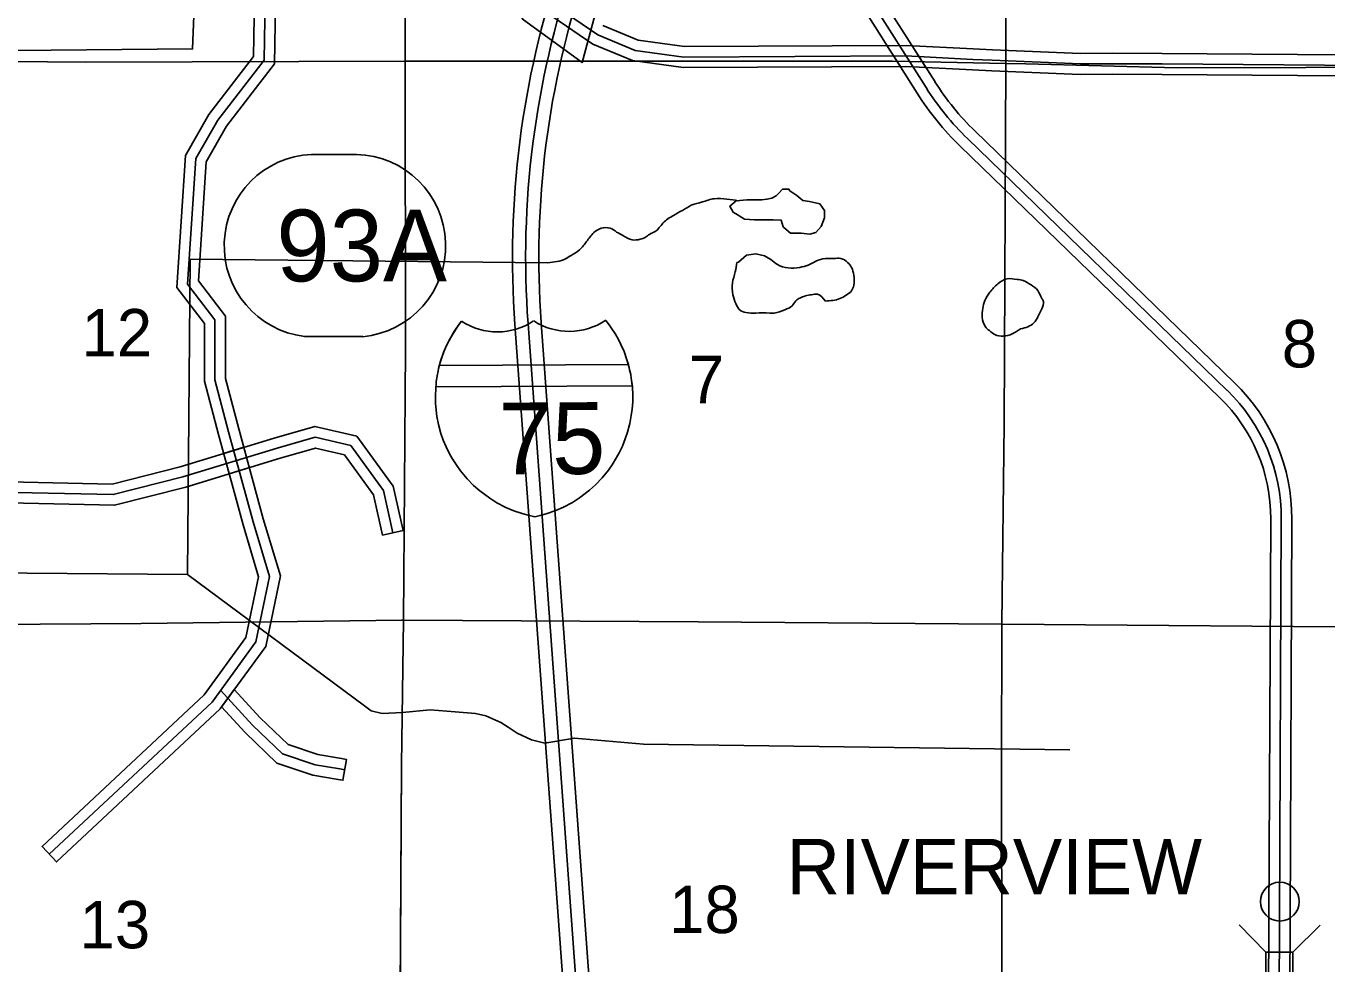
# Model space of a CAD drawing. Extents: x 380424 to 701066, y 1117407 to 1412949.
# Drawn here: x 538699 to 551026, y 1285659 to 1294552 of the extents above; entities that cross this region are included whole.
import ezdxf

# ---------------------------------------------------------------- set-up
doc = ezdxf.new("R2010")
doc.units = 0
for name, color, linetype in [('Bridges and Drawbridges US Highways', 7, 'Continuous'), ('Communities Names with Post Office', 7, 'Continuous'), ('County Route Divided Highway Outline and Fill', 7, 'Continuous'), ('County Routes Highway Center Lines', 7, 'Continuous'), ('Interstate Divided Highway Outline and Fill', 7, 'Continuous'), ('Interstate Highway Center Lines', 7, 'Continuous'), ('Lakes and Ponds', 7, 'Continuous'), ('Local Roads Divided Highway Outline and Fill', 7, 'Continuous'), ('Local Roads Paved', 7, 'Continuous'), ('Masks for Road Features', 7, 'Continuous'), ('Narrow Canals', 7, 'Continuous'), ('Roadshields Interstates', 7, 'Continuous'), ('Section Lines', 7, 'Continuous'), ('Section Numbers', 7, 'Continuous'), ('Town Centers', 7, 'Continuous'), ('Township  and Range lines', 7, 'Continuous'), ('US Route Divided Highway Outline and Fill', 7, 'Continuous'), ('US Routes Highway Center Lines', 7, 'Continuous')]:
    doc.layers.add(name, color=color, linetype=linetype)

msp = doc.modelspace()

# ---------------------------------------------------------------- linework, layer by layer
at = {"layer": 'Bridges and Drawbridges US Highways'}
for p, q in [((550457, 1285773), (550203, 1286030)), ((550713, 1285772), (550971, 1286026))]:
    msp.add_line(p, q, dxfattribs=at)
msp.add_lwpolyline([(550713, 1285772), (550708, 1284760), (550452, 1284761), (550457, 1285773)], close=True, dxfattribs=at)
at = {"layer": 'County Route Divided Highway Outline and Fill'}
for points in [[(577649, 1294028), (553319, 1294063), (549473, 1294092), (549005, 1294095), (548696, 1294092), (547856, 1294127), (547673, 1294135), (547041, 1294168), (544931, 1294158), (544450, 1294224), (544073, 1294379), (543694, 1294639)], [(544169, 1294556), (544503, 1294419), (544944, 1294358), (547046, 1294368), (547682, 1294335), (547865, 1294327), (548699, 1294292), (549005, 1294295), (549474, 1294292), (553320, 1294263), (577489, 1294228)]]:
    msp.add_lwpolyline(points, dxfattribs=at)
at = {"layer": 'County Routes Highway Center Lines'}
msp.add_lwpolyline([(543754, 1294719), (544121, 1294468), (544477, 1294321), (544937, 1294258), (547043, 1294268), (547678, 1294235), (547861, 1294227), (548698, 1294192), (549005, 1294195), (549473, 1294192), (553320, 1294163), (577569, 1294128)], dxfattribs=at)
at = {"layer": 'Interstate Divided Highway Outline and Fill'}
for p, q in [((543335, 1291721), (544032, 1282186)), ((544281, 1282205), (543584, 1291739))]:
    msp.add_line(p, q, dxfattribs=at)
for radius in [8705, 8455]:
    msp.add_arc((552017, 1292356), radius, 161.3221, 184.1801, dxfattribs=at)
at = {"layer": 'Interstate Highway Center Lines'}
msp.add_line((543460, 1291730), (544156, 1282196), dxfattribs=at)
msp.add_arc((552017, 1292356), 8580, 161.3221, 184.1801, dxfattribs=at)
at = {"layer": 'Lakes and Ponds'}
msp.add_lwpolyline([(545426, 1292773), (545513, 1292722), (545607, 1292715), (545715, 1292715), (545785, 1292715), (545859, 1292712), (545879, 1292648), (545886, 1292642), (545947, 1292588), (546051, 1292588), (546131, 1292578), (546188, 1292594), (546239, 1292652), (546272, 1292732), (546272, 1292803), (546225, 1292867), (546128, 1292887), (546064, 1292897), (546007, 1292944), (545943, 1292988), (545933, 1293005), (545873, 1293005), (545842, 1292971), (545812, 1292941), (545772, 1292920), (545725, 1292910), (545675, 1292904), (545624, 1292904), (545533, 1292904), (545433, 1292894), (545372, 1292843), (545406, 1292786), (545425, 1292773)], close=True, dxfattribs=at)
msp.add_lwpolyline([(545439, 1292309), (545456, 1292312), (545530, 1292379), (545621, 1292393), (545701, 1292373), (545763, 1292337)], dxfattribs=at)
for points in [[(546279, 1291944), (546205, 1292010), (546147, 1292005), (546036, 1291973), (546000, 1291947), (545963, 1291899), (545894, 1291862), (545794, 1291831), (545751, 1291831), (545620, 1291831), (545525, 1291836), (545466, 1291862), (545430, 1291920), (545403, 1292005), (545398, 1292116), (545424, 1292221), (545439, 1292309)], [(545763, 1292337), (545825, 1292290), (545926, 1292258), (546036, 1292264), (546116, 1292285), (546190, 1292322), (546279, 1292348), (546358, 1292348), (546427, 1292348), (546490, 1292311), (546527, 1292264), (546548, 1292190), (546548, 1292095), (546527, 1292042), (546475, 1292000), (546417, 1291968), (546279, 1291944)], [(548130, 1291680), (548257, 1291738), (548294, 1291796), (548331, 1291870), (548346, 1291939), (548331, 1291970), (548294, 1292044), (548230, 1292097), (548156, 1292139), (548098, 1292150), (548003, 1292155), (547914, 1292108), (547840, 1292028), (547792, 1291949), (547771, 1291875), (547766, 1291791), (547797, 1291701), (547834, 1291664), (547887, 1291627), (547966, 1291611), (548130, 1291680)]]:
    msp.add_spline(points, degree=3, dxfattribs=at)
at = {"layer": 'Local Roads Divided Highway Outline and Fill'}
msp.add_lwpolyline([(541147, 1299651), (541056, 1294192), (540600, 1293602), (540408, 1293265), (540334, 1292135), (540591, 1291801), (540591, 1291560), (540591, 1291211), (540717, 1290732), (540949, 1289879), (541111, 1289338), (540972, 1288671), (540540, 1288077), (538988, 1286627), (538851, 1286773), (540390, 1288210), (540785, 1288754), (540905, 1289329), (540757, 1289824), (540523, 1290680), (540391, 1291185), (540391, 1291560), (540391, 1291733), (540130, 1292073), (540211, 1293325), (540433, 1293713), (540857, 1294262), (540947, 1299653)], dxfattribs=at)
for points in [[(541837, 1290665), (541439, 1290756), (541052, 1290646), (540160, 1290374), (539516, 1290210), (537688, 1290248), (537416, 1290302), (537335, 1290315), (536956, 1290307), (536950, 1290107), (537321, 1290115), (537381, 1290105), (537667, 1290049), (539539, 1290009), (540214, 1290181), (541108, 1290454), (541445, 1290550), (541719, 1290487), (541995, 1290106), (542081, 1289725), (542276, 1289769), (542181, 1290191)], [(540674, 1288261), (540919, 1287993), (541185, 1287739), (541466, 1287645), (541691, 1287607), (541738, 1287599), (541705, 1287402), (541658, 1287410), (541418, 1287450), (541079, 1287563), (540776, 1287853), (540554, 1288096)]]:
    msp.add_lwpolyline(points, close=True, dxfattribs=at)
at = {"layer": 'Local Roads Paved'}
for points in [[(541047, 1299652), (540956, 1294227), (540517, 1293658), (540310, 1293295), (540232, 1292104), (540491, 1291767), (540491, 1291560), (540491, 1291198), (540620, 1290706), (540853, 1289851), (541008, 1289334), (540879, 1288713), (540465, 1288143), (538919, 1286700)], [(536953, 1290207), (537328, 1290215), (537399, 1290203), (537677, 1290148), (539527, 1290109), (540187, 1290278), (541080, 1290550), (541442, 1290653), (541778, 1290576), (542088, 1290149), (542179, 1289747)], [(541722, 1287501), (541675, 1287509), (541442, 1287547), (541132, 1287651), (540847, 1287923), (540545, 1288254)]]:
    msp.add_lwpolyline(points, dxfattribs=at)
at = {"layer": 'Masks for Road Features'}
for p, q in [((546863, 1294367), (546990, 1294168)), ((547101, 1294365), (547233, 1294158)), ((540573, 1290500), (540764, 1290558)), ((540625, 1290307), (540817, 1290365)), ((540554, 1288096), (540674, 1288261))]:
    msp.add_line(p, q, dxfattribs=at)
msp.add_lwpolyline([(543594, 1295245), (543405, 1294621), (543972, 1294206), (544138, 1294820)], close=True, dxfattribs=at)
at = {"layer": 'Narrow Canals'}
for points in [[(534481, 1293949), (534771, 1293365), (536895, 1293374), (536922, 1294303), (540279, 1294335), (540379, 1296837), (541350, 1296969), (541841, 1297264), (541587, 1297776), (541624, 1298236), (542984, 1298241)], [(535671, 1293369), (535665, 1289389), (540231, 1289352), (540257, 1292340), (543646, 1292308)], [(540231, 1289352), (541909, 1288107), (541973, 1288059), (542078, 1288033), (542268, 1288043), (542532, 1288070), (542770, 1288049), (542960, 1288033), (543060, 1288012), (543203, 1287948), (543271, 1287906), (543356, 1287848), (543493, 1287785), (543620, 1287753), (543899, 1287801), (544554, 1287743), (548597, 1287690)]]:
    msp.add_lwpolyline(points, dxfattribs=at)
msp.add_spline([(543646, 1292308), (543815, 1292345), (543868, 1292377), (543947, 1292430), (544015, 1292509), (544084, 1292593), (544153, 1292635), (544237, 1292635), (544300, 1292599), (544359, 1292567), (544448, 1292525), (544522, 1292530), (544575, 1292551), (544612, 1292577), (544665, 1292604), (544739, 1292683), (544839, 1292757), (544923, 1292804), (545008, 1292852), (545113, 1292884), (545224, 1292915), (545346, 1292910), (545454, 1292896)], degree=3, dxfattribs=at)
at = {"layer": 'Roadshields Interstates'}
for p, q in [((541831, 1293335), (541407, 1293335)), ((541340, 1291608), (541892, 1291608)), ((544411, 1291342), (542619, 1291332)), ((542619, 1291332), (542621, 1291337)), ((544448, 1291142), (542585, 1291131)), ((544442, 1291192), (544448, 1291142))]:
    msp.add_line(p, q, dxfattribs=at)
for points in [[(542828, 1291753), (542797, 1291712), (542777, 1291682), (542739, 1291622), (542711, 1291571), (542688, 1291524), (542659, 1291456), (542631, 1291375), (542612, 1291304), (542607, 1291281)], [(542621, 1291337), (542619, 1291332), (542631, 1291375), (542659, 1291456), (542688, 1291524), (542711, 1291571), (542739, 1291622), (542777, 1291682), (542797, 1291712), (542828, 1291753)], [(544423, 1291292), (544418, 1291315), (544398, 1291386), (544370, 1291466), (544340, 1291534), (544316, 1291581), (544288, 1291631), (544249, 1291691), (544228, 1291720), (544197, 1291761)], [(544197, 1291761), (544228, 1291720), (544249, 1291691), (544288, 1291631), (544316, 1291581), (544340, 1291534), (544370, 1291466), (544398, 1291386), (544411, 1291342)], [(542607, 1291281), (542598, 1291236), (542597, 1291231)], [(544434, 1291242), (544433, 1291247), (544423, 1291292)], [(542590, 1291181), (542588, 1291164), (542584, 1291120), (542581, 1291042), (542583, 1290977), (542588, 1290911), (542596, 1290849), (542612, 1290773), (542634, 1290690), (542656, 1290627), (542684, 1290561), (542715, 1290496), (542740, 1290451), (542783, 1290384), (542819, 1290334), (542881, 1290260), (542944, 1290196), (543002, 1290145), (543096, 1290075), (543165, 1290032), (543250, 1289988), (543324, 1289956), (543413, 1289926), (543473, 1289911), (543523, 1289900)], [(542585, 1291131), (542585, 1291133), (542584, 1291120), (542581, 1291042), (542583, 1290977), (542588, 1290911), (542596, 1290849), (542612, 1290773), (542634, 1290690), (542656, 1290627), (542684, 1290561), (542715, 1290496), (542740, 1290451), (542783, 1290384), (542819, 1290334), (542881, 1290260), (542944, 1290196), (543002, 1290145), (543096, 1290075), (543165, 1290032), (543250, 1289988), (543324, 1289956), (543413, 1289926), (543473, 1289911), (543523, 1289900)], [(543523, 1289900), (543473, 1289911), (543413, 1289926), (543324, 1289956), (543250, 1289988), (543165, 1290032), (543096, 1290075), (543002, 1290145), (542944, 1290196), (542881, 1290260), (542819, 1290334), (542783, 1290384), (542740, 1290451), (542715, 1290496), (542684, 1290561), (542656, 1290627), (542634, 1290690), (542612, 1290773), (542596, 1290849), (542588, 1290911), (542583, 1290977), (542581, 1291042), (542584, 1291120), (542585, 1291131)], [(542597, 1291231), (542590, 1291181)], [(543523, 1289900), (543574, 1289911), (543633, 1289928), (543722, 1289959), (543796, 1289991), (543880, 1290036), (543949, 1290080), (544042, 1290151), (544099, 1290202), (544162, 1290268), (544223, 1290342), (544258, 1290393), (544300, 1290460), (544324, 1290505), (544355, 1290570), (544382, 1290637), (544403, 1290700), (544425, 1290783), (544439, 1290859), (544447, 1290921), (544452, 1290988), (544453, 1291053), (544449, 1291130), (544444, 1291174), (544442, 1291192)], [(543523, 1289900), (543574, 1289911), (543633, 1289928), (543722, 1289959), (543796, 1289991), (543880, 1290036), (543949, 1290080), (544042, 1290151), (544099, 1290202), (544162, 1290268), (544223, 1290342), (544258, 1290393), (544300, 1290460), (544324, 1290505), (544355, 1290570), (544382, 1290637), (544403, 1290700), (544425, 1290783), (544439, 1290859), (544447, 1290921), (544452, 1290988), (544453, 1291053), (544449, 1291130), (544444, 1291174), (544442, 1291192)], [(544448, 1291142), (544449, 1291130), (544453, 1291053), (544452, 1290988), (544447, 1290921), (544439, 1290859), (544425, 1290783), (544403, 1290700), (544382, 1290637), (544355, 1290570), (544324, 1290505), (544300, 1290460), (544258, 1290393), (544223, 1290342), (544162, 1290268), (544099, 1290202), (544042, 1290151), (543949, 1290080), (543880, 1290036), (543796, 1289991), (543722, 1289959), (543633, 1289928), (543574, 1289911), (543523, 1289900)], [(544442, 1291192), (544434, 1291242)]]:
    msp.add_lwpolyline(points, dxfattribs=at)
for centre, radius, start, end in [((541446, 1292469), 867, 92.5593, 262.976), ((541812, 1292469), 866, 275.3165, 88.7037), ((543726, 1291046), 1143, 141.7497, 165.5088), ((543169, 1292271), 619, 236.7027, 303.7432), ((543169, 1292271), 619, 236.7027, 303.7432), ((543169, 1292271), 619, 236.7027, 303.7432), ((543851, 1292280), 623, 237.1623, 303.7264), ((543851, 1292280), 623, 237.1623, 303.7264), ((543851, 1292280), 623, 237.1623, 303.7264)]:
    msp.add_arc(centre, radius, start, end, dxfattribs=at)
at = {"layer": 'Section Lines'}
for points in [[(542312, 1299491), (542312, 1299480), (542298, 1297086), (542295, 1294219), (539266, 1294209), (537082, 1294229), (537070, 1294229), (537080, 1294384), (537092, 1294985), (537088, 1297845), (537086, 1299490), (537084, 1299501), (539444, 1299487), (542305, 1299491)], [(548002, 1299470), (547990, 1294212), (547990, 1294196), (546915, 1294218), (544769, 1294218), (542307, 1294219), (542295, 1294219), (542298, 1297086), (542312, 1299480), (542312, 1299491), (545296, 1299469)], [(553307, 1299491), (553307, 1299468), (553271, 1298758), (553281, 1294188), (553281, 1294166), (553279, 1294166), (549616, 1294155), (548180, 1294193), (547990, 1294196), (547990, 1294212), (548002, 1299470), (553275, 1299491)], [(542295, 1294219), (542295, 1294211), (542297, 1291485), (542279, 1288918), (542262, 1288918), (539792, 1288887), (536918, 1288867), (536922, 1289281), (536933, 1291223), (536994, 1292700), (537070, 1294219), (537070, 1294229), (537082, 1294229), (539266, 1294209)], [(547990, 1294196), (547976, 1290776), (547953, 1288886), (547953, 1288880), (545074, 1288903), (542279, 1288918), (542297, 1291485), (542295, 1294211), (542295, 1294219), (542307, 1294219), (544769, 1294218), (546915, 1294218)], [(553281, 1294166), (553317, 1290222), (553297, 1288855), (551899, 1288849), (547958, 1288880), (547953, 1288880), (547953, 1288886), (547976, 1290776), (547990, 1294196), (548180, 1294193), (549616, 1294155), (553279, 1294166)], [(542279, 1288918), (542261, 1287549), (542237, 1283539), (536930, 1283582), (536927, 1287548), (536918, 1288867), (539792, 1288887), (542262, 1288918)], [(547953, 1288880), (547949, 1287540), (547956, 1283608), (542237, 1283539), (542261, 1287549), (542279, 1288918), (545074, 1288903)], [(553297, 1288855), (553286, 1287512), (553246, 1283629), (547956, 1283608), (547949, 1287540), (547953, 1288880), (547958, 1288880), (551899, 1288849)]]:
    msp.add_lwpolyline(points, close=True, dxfattribs=at)
at = {"layer": 'Town Centers'}
msp.add_circle((550588, 1286251), 184, dxfattribs=at)
at = {"layer": 'Township  and Range lines'}
for p, q in [((542298, 1297086), (542295, 1294219)), ((542295, 1294219), (542295, 1294211)), ((542295, 1294211), (542297, 1291485)), ((542297, 1291485), (542279, 1288918)), ((542279, 1288918), (542261, 1287549)), ((542261, 1287549), (542237, 1283539))]:
    msp.add_line(p, q, dxfattribs=at)
at = {"layer": 'US Route Divided Highway Outline and Fill'}
for p, q in [((546382, 1295498), (547319, 1294022)), ((547150, 1293915), (546214, 1295391)), ((547697, 1293557), (550159, 1291170)), ((550019, 1291026), (547558, 1293413))]:
    msp.add_line(p, q, dxfattribs=at)
msp.add_lwpolyline([(550702, 1289878), (550685, 1286067), (550662, 1281039), (550656, 1279761), (550656, 1279441), (550456, 1279441), (550456, 1279762), (550462, 1281040), (550485, 1286068), (550502, 1289878)], dxfattribs=at)
for centre, radius, start, end in [((549475, 1295390), 2554, 212.3999, 225.8732), ((549475, 1295390), 2754, 212.3999, 225.8732), ((548913, 1289886), 1789, 359.7387, 45.8732), ((548913, 1289886), 1589, 359.7387, 45.8732)]:
    msp.add_arc(centre, radius, start, end, dxfattribs=at)
at = {"layer": 'US Routes Highway Center Lines'}
for p, q in [((547235, 1293968), (546298, 1295444)), ((550089, 1291098), (547628, 1293485))]:
    msp.add_line(p, q, dxfattribs=at)
msp.add_lwpolyline([(550548, 1278025), (550556, 1279761), (550556, 1279761), (550562, 1281040), (550585, 1286067), (550602, 1289878)], dxfattribs=at)
for centre, radius, start, end in [((549475, 1295390), 2654, 212.3999, 225.8732), ((548913, 1289886), 1689, 359.7387, 45.8732)]:
    msp.add_arc(centre, radius, start, end, dxfattribs=at)

# ---------------------------------------------------------------- texts
at = {"layer": 'Communities Names with Post Office'}
msp.add_text('RIVERVIEW', height=525, rotation=0.0005, dxfattribs=at).set_placement((545911, 1286321))
at = {"layer": 'Roadshields Interstates'}
for s, rotation, p in [('93A', 0.0005, (541073, 1292131)), ('75', 0.3336, (543183, 1290301))]:
    msp.add_text(s, height=680, rotation=rotation, dxfattribs=at).set_placement(p)
at = {"layer": 'Section Numbers'}
for s, p in [('12', (539226, 1291419)), ('8', (550607, 1291315)), ('7', (544984, 1290976)), ('18', (544798, 1285952)), ('13', (539207, 1285808))]:
    msp.add_text(s, height=450, dxfattribs=at).set_placement(p)

doc.saveas('drawing.dxf')
